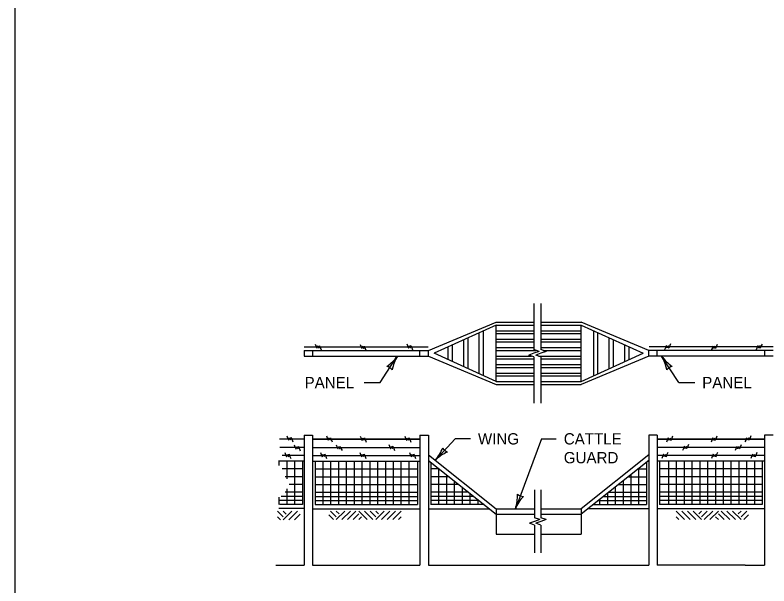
# Model space of a CAD drawing. Extents: x 49991.4 to 50021, y 49987.6 to 50011.4.
# Drawn here: x 49999.384 to 50003.386, y 49992.938 to 49995.969 of the extents above; entities that cross this region are included whole.
import ezdxf

# ---------------------------------------------------------------- set-up
doc = ezdxf.new("R2010")
doc.units = 0
for name, color, linetype in [('Level 1', 7, 'Continuous'), ('Level 2', 7, 'Continuous'), ('Level 3', 7, 'Continuous'), ('Level 4', 7, 'Continuous'), ('Level 6', 7, 'Continuous')]:
    doc.layers.add(name, color=color, linetype=linetype)

msp = doc.modelspace()

# ---------------------------------------------------------------- linework, layer by layer
at = {"layer": 'Level 1'}
for p, q in [((50001.5785, 49994.1885), (50001.9385, 49994.3385)), ((50001.9385, 49994.3235), (50001.6085, 49994.1735)), ((50001.9385, 49994.3385), (50002.1384, 49994.3385)), ((50001.9385, 49994.0235), (50001.9385, 49994.3235)), ((50001.9385, 49994.3235), (50002.1384, 49994.3235)), ((50002.1756, 49994.3385), (50002.3885, 49994.3385)), ((50002.1756, 49994.3235), (50002.3885, 49994.3235)), ((50002.7485, 49994.1885), (50002.3885, 49994.3385)), ((50002.3885, 49994.3235), (50002.7185, 49994.1735)), ((50002.3885, 49994.0235), (50002.3885, 49994.3235)), ((50001.8485, 49994.064), (50001.8485, 49994.2821)), ((50001.871, 49994.0537), (50001.871, 49994.2923)), ((50001.9385, 49994.2935), (50002.1384, 49994.2935)), ((50001.9385, 49994.2785), (50002.1384, 49994.2785)), ((50002.1756, 49994.2935), (50002.3885, 49994.2935)), ((50002.1756, 49994.2785), (50002.3885, 49994.2785)), ((50002.456, 49994.0537), (50002.456, 49994.2923)), ((50002.4785, 49994.064), (50002.4785, 49994.2821)), ((50001.766, 49994.1015), (50001.766, 49994.2443)), ((50001.7885, 49994.0913), (50001.7885, 49994.2554)), ((50001.9385, 49994.2485), (50002.1384, 49994.2485)), ((50001.9385, 49994.2335), (50002.1384, 49994.2335)), ((50002.1756, 49994.2485), (50002.3885, 49994.2485)), ((50002.1756, 49994.2335), (50002.3885, 49994.2335)), ((50002.5385, 49994.0913), (50002.5385, 49994.2554)), ((50002.561, 49994.1015), (50002.561, 49994.2443)), ((50000.9185, 49994.208), (50001.5771, 49994.208)), ((50000.9185, 49994.1885), (50000.9185, 49994.1585)), ((50000.9185, 49994.1885), (50001.5785, 49994.1885)), ((50000.9635, 49994.1885), (50000.9635, 49994.1585)), ((50001.5335, 49994.1585), (50001.5335, 49994.1885)), ((50001.5785, 49994.1585), (50001.5785, 49994.1885)), ((50001.6835, 49994.1389), (50001.6835, 49994.2074)), ((50001.706, 49994.1287), (50001.706, 49994.2176)), ((50001.706, 49994.1287), (50001.706, 49994.2176)), ((50001.9385, 49994.2035), (50002.1384, 49994.2035)), ((50001.9385, 49994.1885), (50002.1508, 49994.1885)), ((50002.1756, 49994.2035), (50002.3885, 49994.2035)), ((50002.188, 49994.1885), (50002.3885, 49994.1885)), ((50002.621, 49994.1287), (50002.621, 49994.2176)), ((50002.621, 49994.1287), (50002.621, 49994.2176)), ((50002.621, 49994.1287), (50002.621, 49994.2176)), ((50002.6435, 49994.1389), (50002.6435, 49994.2074)), ((50002.7485, 49994.1585), (50002.7485, 49994.1885)), ((50003.4085, 49994.1885), (50002.7485, 49994.1885)), ((50003.4085, 49994.208), (50002.7499, 49994.208)), ((50002.7935, 49994.1585), (50002.7935, 49994.1885)), ((50003.3635, 49994.1885), (50003.3635, 49994.1585)), ((50000.9185, 49994.1585), (50001.5785, 49994.1585)), ((50001.5785, 49994.1585), (50001.9385, 49994.0085)), ((50001.9385, 49994.0235), (50001.6085, 49994.1735)), ((50001.9385, 49994.1585), (50002.126, 49994.1585)), ((50002.1632, 49994.1585), (50002.3885, 49994.1585)), ((50002.3885, 49994.0235), (50002.7185, 49994.1735)), ((50002.7485, 49994.1585), (50002.3885, 49994.0085)), ((50003.4085, 49994.1585), (50002.7485, 49994.1585)), ((50001.9385, 49994.1435), (50002.1384, 49994.1435)), ((50001.9385, 49994.1135), (50002.1384, 49994.1135)), ((50002.1756, 49994.1435), (50002.3885, 49994.1435)), ((50002.1756, 49994.1135), (50002.3885, 49994.1135)), ((50001.9385, 49994.0985), (50002.1384, 49994.0985)), ((50001.9385, 49994.0685), (50002.1384, 49994.0685)), ((50002.1756, 49994.0985), (50002.3885, 49994.0985)), ((50002.1756, 49994.0685), (50002.3885, 49994.0685)), ((50001.9385, 49994.0535), (50002.1384, 49994.0535)), ((50002.1756, 49994.0535), (50002.3885, 49994.0535)), ((50001.9385, 49994.0235), (50002.1384, 49994.0235)), ((50001.9385, 49994.0085), (50002.1384, 49994.0085)), ((50002.1756, 49994.0235), (50002.3885, 49994.0235)), ((50002.1756, 49994.0085), (50002.3885, 49994.0085)), ((50000.9185, 49993.7184), (50000.7881, 49993.7184)), ((50000.918, 49993.7169), (50000.918, 49993.7169)), ((50000.9185, 49993.7385), (50000.9635, 49993.7385)), ((50000.9185, 49993.7385), (50000.9185, 49993.3485)), ((50000.9185, 49993.7235), (50000.9185, 49993.7235)), ((50001.5306, 49993.7177), (50000.963, 49993.7177)), ((50000.9635, 49993.7385), (50000.9635, 49993.3485)), ((50000.9635, 49993.7169), (50001.5335, 49993.7169)), ((50001.5335, 49993.7385), (50001.5335, 49993.3485)), ((50001.5335, 49993.7385), (50001.5785, 49993.7385)), ((50001.5785, 49993.7385), (50001.5785, 49993.3485)), ((50002.7935, 49993.7385), (50002.7485, 49993.7385)), ((50002.7485, 49993.7385), (50002.7485, 49993.3485)), ((50002.7935, 49993.7385), (50002.7935, 49993.3485)), ((50003.3635, 49993.7169), (50002.7935, 49993.7169)), ((50002.7964, 49993.7177), (50003.364, 49993.7177)), ((50003.3635, 49993.7385), (50003.3635, 49993.3485)), ((50003.4085, 49993.7385), (50003.3635, 49993.7385)), ((50000.918, 49993.6736), (50000.7889, 49993.6736)), ((50000.918, 49993.6736), (50000.9185, 49993.6736)), ((50000.9635, 49993.6736), (50001.5345, 49993.6736)), ((50003.3635, 49993.6736), (50002.7925, 49993.6736)), ((50000.918, 49993.6302), (50000.8021, 49993.6302)), ((50000.918, 49993.6302), (50000.9185, 49993.6302)), ((50000.9635, 49993.6302), (50001.5335, 49993.6302)), ((50001.5785, 49993.6335), (50001.9385, 49993.3485)), ((50002.7485, 49993.6335), (50002.3885, 49993.3485)), ((50003.3635, 49993.6302), (50002.7935, 49993.6302)), ((50000.918, 49993.6014), (50000.7821, 49993.6014)), ((50000.7848, 49993.6014), (50000.7848, 49993.5778)), ((50000.8263, 49993.6014), (50000.8263, 49993.5071)), ((50000.8678, 49993.6014), (50000.8678, 49993.3704)), ((50000.9093, 49993.6014), (50000.9093, 49993.3704)), ((50000.9635, 49993.6014), (50001.5207, 49993.6014)), ((50000.9761, 49993.6014), (50000.9761, 49993.3704)), ((50001.0176, 49993.6014), (50001.0176, 49993.3704)), ((50001.0591, 49993.6014), (50001.0591, 49993.3704)), ((50001.1006, 49993.6014), (50001.1006, 49993.3704)), ((50001.1421, 49993.6014), (50001.1421, 49993.3704)), ((50001.1836, 49993.6014), (50001.1836, 49993.3704)), ((50001.2251, 49993.6014), (50001.2251, 49993.3704)), ((50001.2666, 49993.6014), (50001.2666, 49993.3704)), ((50001.3081, 49993.6014), (50001.3081, 49993.3704)), ((50001.3496, 49993.6014), (50001.3496, 49993.3704)), ((50001.3911, 49993.6014), (50001.3911, 49993.3704)), ((50001.4326, 49993.6014), (50001.4326, 49993.3704)), ((50001.4741, 49993.6014), (50001.4741, 49993.3704)), ((50001.521, 49993.6014), (50001.521, 49993.5749)), ((50001.521, 49993.6014), (50001.5335, 49993.6014)), ((50001.5812, 49993.6014), (50001.5782, 49993.6014)), ((50001.5785, 49993.6035), (50001.9385, 49993.3185)), ((50001.5785, 49993.6014), (50001.5785, 49993.3605)), ((50001.5909, 49993.5924), (50001.5909, 49993.3704)), ((50002.7485, 49993.6035), (50002.3885, 49993.3185)), ((50002.7361, 49993.5924), (50002.7361, 49993.3704)), ((50002.7458, 49993.6014), (50002.7488, 49993.6014)), ((50002.7458, 49993.6014), (50002.7488, 49993.6014)), ((50002.7485, 49993.6014), (50002.7485, 49993.3605)), ((50002.7485, 49993.6014), (50002.7485, 49993.3605)), ((50002.806, 49993.6014), (50002.7935, 49993.6014)), ((50002.806, 49993.6014), (50002.806, 49993.5749)), ((50003.3635, 49993.6014), (50002.8063, 49993.6014)), ((50002.8529, 49993.6014), (50002.8529, 49993.3704)), ((50002.8944, 49993.6014), (50002.8944, 49993.3704)), ((50002.9359, 49993.6014), (50002.9359, 49993.3704)), ((50002.9774, 49993.6014), (50002.9774, 49993.3704)), ((50003.0189, 49993.6014), (50003.0189, 49993.3704)), ((50003.0604, 49993.6014), (50003.0604, 49993.3704)), ((50003.1019, 49993.6014), (50003.1019, 49993.3704)), ((50003.1434, 49993.6014), (50003.1434, 49993.3704)), ((50003.1849, 49993.6014), (50003.1849, 49993.3704)), ((50003.2264, 49993.6014), (50003.2264, 49993.3704)), ((50003.2679, 49993.6014), (50003.2679, 49993.3704)), ((50003.3094, 49993.6014), (50003.3094, 49993.3704)), ((50003.3509, 49993.6014), (50003.3509, 49993.3704)), ((50000.9093, 49993.5599), (50000.8016, 49993.5599)), ((50000.9761, 49993.5599), (50001.5207, 49993.5599)), ((50001.521, 49993.5749), (50001.521, 49993.3704)), ((50001.6339, 49993.5599), (50001.5914, 49993.5599)), ((50001.6324, 49993.5598), (50001.6324, 49993.3704)), ((50002.6931, 49993.5599), (50002.7356, 49993.5599)), ((50002.6946, 49993.5598), (50002.6946, 49993.3704)), ((50002.806, 49993.5749), (50002.806, 49993.3704)), ((50003.3509, 49993.5599), (50002.8063, 49993.5599)), ((50000.9093, 49993.5184), (50000.8182, 49993.5184)), ((50000.9761, 49993.5184), (50001.5207, 49993.5184)), ((50001.6847, 49993.5184), (50001.5906, 49993.5184)), ((50001.6739, 49993.5262), (50001.6739, 49993.3704)), ((50002.6423, 49993.5184), (50002.7364, 49993.5184)), ((50002.6531, 49993.5262), (50002.6531, 49993.3704)), ((50003.3509, 49993.5184), (50002.8063, 49993.5184)), ((50000.9093, 49993.4769), (50000.8394, 49993.4769)), ((50000.9761, 49993.4769), (50001.5207, 49993.4769)), ((50001.7376, 49993.4769), (50001.5906, 49993.4769)), ((50001.7154, 49993.4947), (50001.7154, 49993.3704)), ((50002.5894, 49993.4769), (50002.7364, 49993.4769)), ((50002.6116, 49993.4947), (50002.6116, 49993.3704)), ((50003.3509, 49993.4769), (50002.8063, 49993.4769)), ((50000.9093, 49993.4354), (50000.8171, 49993.4354)), ((50000.8263, 49993.4542), (50000.8263, 49993.3704)), ((50000.9761, 49993.4354), (50001.5207, 49993.4354)), ((50001.7884, 49993.4354), (50001.5906, 49993.4354)), ((50001.7569, 49993.461), (50001.7569, 49993.3704)), ((50001.7985, 49993.429), (50001.7985, 49993.3704)), ((50002.5285, 49993.429), (50002.5285, 49993.3704)), ((50002.5386, 49993.4354), (50002.7364, 49993.4354)), ((50002.5701, 49993.461), (50002.5701, 49993.3704)), ((50003.3509, 49993.4354), (50002.8063, 49993.4354)), ((50000.9093, 49993.392), (50000.7818, 49993.392)), ((50000.7848, 49993.4089), (50000.7848, 49993.3704)), ((50000.9093, 49993.4137), (50000.7972, 49993.4137)), ((50000.9761, 49993.4137), (50001.5206, 49993.4137)), ((50000.9761, 49993.392), (50001.5212, 49993.392)), ((50001.8453, 49993.392), (50001.5908, 49993.392)), ((50001.8183, 49993.4137), (50001.5914, 49993.4137)), ((50001.8399, 49993.3965), (50001.8399, 49993.3704)), ((50002.4817, 49993.392), (50002.7362, 49993.392)), ((50002.4871, 49993.3965), (50002.4871, 49993.3704)), ((50002.5087, 49993.4137), (50002.7356, 49993.4137)), ((50003.3509, 49993.392), (50002.8058, 49993.392)), ((50003.3509, 49993.4137), (50002.8064, 49993.4137)), ((50000.918, 49993.3486), (50000.7844, 49993.3486)), ((50000.9093, 49993.3704), (50000.7889, 49993.3704)), ((50000.9635, 49993.3485), (50001.5335, 49993.3485)), ((50000.9761, 49993.3704), (50001.5209, 49993.3704)), ((50001.5785, 49993.3485), (50001.8992, 49993.3485)), ((50001.8735, 49993.3704), (50001.5912, 49993.3704)), ((50001.9385, 49993.3485), (50001.9385, 49993.3185)), ((50001.9385, 49993.3485), (50002.1416, 49993.3485)), ((50002.176, 49993.3485), (50002.3885, 49993.3485)), ((50002.3885, 49993.3485), (50002.3885, 49993.3185)), ((50002.7485, 49993.3485), (50002.4278, 49993.3485)), ((50002.4535, 49993.3704), (50002.7358, 49993.3704)), ((50003.3635, 49993.3485), (50002.7935, 49993.3485)), ((50003.3509, 49993.3704), (50002.8061, 49993.3704)), ((50000.8075, 49993.3048), (50000.7775, 49993.3348)), ((50000.8075, 49993.2898), (50000.8525, 49993.3348)), ((50000.8075, 49993.2898), (50000.8525, 49993.3348)), ((50000.8225, 49993.3198), (50000.8075, 49993.3348)), ((50000.8375, 49993.2898), (50000.8825, 49993.3348)), ((50000.8375, 49993.2898), (50000.8825, 49993.3348)), ((50000.8675, 49993.2898), (50000.8966, 49993.3189)), ((50001.0737, 49993.2909), (50001.0496, 49993.315)), ((50001.0887, 49993.3059), (50001.0587, 49993.3359)), ((50001.0887, 49993.2909), (50001.1337, 49993.3359)), ((50001.0887, 49993.2909), (50001.1337, 49993.3359)), ((50001.1037, 49993.3209), (50001.0887, 49993.3359)), ((50001.1187, 49993.2909), (50001.1637, 49993.3359)), ((50001.1187, 49993.2909), (50001.1637, 49993.3359)), ((50001.1487, 49993.2909), (50001.1937, 49993.3359)), ((50001.1487, 49993.2909), (50001.1937, 49993.3359)), ((50001.1787, 49993.2909), (50001.2087, 49993.3209)), ((50001.2537, 49993.2909), (50001.2087, 49993.3359)), ((50001.2837, 49993.2909), (50001.2387, 49993.3359)), ((50001.2987, 49993.3059), (50001.2687, 49993.3359)), ((50001.2987, 49993.2909), (50001.3437, 49993.3359)), ((50001.2987, 49993.2909), (50001.3437, 49993.3359)), ((50001.3137, 49993.3209), (50001.2987, 49993.3359)), ((50001.3287, 49993.2909), (50001.3737, 49993.3359)), ((50001.3287, 49993.2909), (50001.3737, 49993.3359)), ((50001.3587, 49993.2909), (50001.4037, 49993.3359)), ((50001.3587, 49993.2909), (50001.4037, 49993.3359)), ((50001.3887, 49993.2909), (50001.4337, 49993.3359)), ((50001.3887, 49993.2909), (50001.4337, 49993.3359)), ((50001.9385, 49993.3185), (50002.1416, 49993.3185)), ((50002.176, 49993.3185), (50002.3885, 49993.3185)), ((50002.9383, 49993.2909), (50002.8933, 49993.3359)), ((50002.9383, 49993.2909), (50002.8933, 49993.3359)), ((50002.9683, 49993.2909), (50002.9233, 49993.3359)), ((50002.9683, 49993.2909), (50002.9233, 49993.3359)), ((50002.9983, 49993.2909), (50002.9533, 49993.3359)), ((50002.9983, 49993.2909), (50002.9533, 49993.3359)), ((50003.0283, 49993.2909), (50002.9833, 49993.3359)), ((50003.0283, 49993.2909), (50002.9833, 49993.3359)), ((50003.0133, 49993.3209), (50003.0283, 49993.3359)), ((50003.0283, 49993.3059), (50003.0583, 49993.3359)), ((50003.0433, 49993.2909), (50003.0883, 49993.3359)), ((50003.0733, 49993.2909), (50003.1183, 49993.3359)), ((50003.1483, 49993.2909), (50003.1183, 49993.3209)), ((50003.1783, 49993.2909), (50003.1333, 49993.3359)), ((50003.1783, 49993.2909), (50003.1333, 49993.3359)), ((50003.2083, 49993.2909), (50003.1633, 49993.3359)), ((50003.2083, 49993.2909), (50003.1633, 49993.3359)), ((50003.2383, 49993.2909), (50003.1933, 49993.3359)), ((50003.2383, 49993.2909), (50003.1933, 49993.3359)), ((50003.2233, 49993.3209), (50003.2383, 49993.3359)), ((50003.2383, 49993.3059), (50003.2683, 49993.3359)), ((50003.2533, 49993.2909), (50003.2774, 49993.315)), ((50000.7925, 49993.2898), (50000.7767, 49993.3056)), ((50000.8675, 49993.2898), (50000.8795, 49993.3018)), ((50001.2087, 49993.2909), (50001.2237, 49993.3059)), ((50001.4187, 49993.2909), (50001.4337, 49993.3059)), ((50002.9083, 49993.2909), (50002.8933, 49993.3059)), ((50003.1183, 49993.2909), (50003.1033, 49993.3059))]:
    msp.add_line(p, q, dxfattribs=at)
msp.add_lwpolyline([(49999.3835, 49998.9992), (50016.7501, 49998.9992), (50016.7501, 49987.7988), (49999.3835, 49987.7988)], close=True, dxfattribs=at)
for points in [[(50000.9773, 49994.2227), (50000.9878, 49994.2017), (50000.9878, 49994.2122), (50000.9983, 49994.2017), (50000.9983, 49994.2122), (50001.0088, 49994.1912)], [(50001.2153, 49994.2209), (50001.2258, 49994.1999), (50001.2258, 49994.2104), (50001.2363, 49994.1999), (50001.2363, 49994.2104), (50001.2468, 49994.1894)], [(50001.463, 49994.2239), (50001.4735, 49994.2029), (50001.4735, 49994.2134), (50001.484, 49994.2029), (50001.484, 49994.2134), (50001.4945, 49994.1924)], [(50002.864, 49994.2239), (50002.8535, 49994.2029), (50002.8535, 49994.2134), (50002.843, 49994.2029), (50002.843, 49994.2134), (50002.8325, 49994.1924)], [(50003.1117, 49994.2209), (50003.1012, 49994.1999), (50003.1012, 49994.2104), (50003.0907, 49994.1999), (50003.0907, 49994.2104), (50003.0802, 49994.1894)], [(50003.3497, 49994.2227), (50003.3392, 49994.2017), (50003.3392, 49994.2122), (50003.3287, 49994.2017), (50003.3287, 49994.2122), (50003.3182, 49994.1912)], [(50000.8267, 49993.7352), (50000.8372, 49993.7142), (50000.8372, 49993.7247), (50000.8477, 49993.7142), (50000.8477, 49993.7247), (50000.8582, 49993.7037)], [(50001.0365, 49993.7345), (50001.047, 49993.7135), (50001.047, 49993.724), (50001.0575, 49993.7135), (50001.0575, 49993.724), (50001.068, 49993.703)], [(50001.2167, 49993.7334), (50001.2272, 49993.7124), (50001.2272, 49993.7229), (50001.2377, 49993.7124), (50001.2377, 49993.7229), (50001.2482, 49993.7019)], [(50001.4531, 49993.7337), (50001.4636, 49993.7126), (50001.4636, 49993.7232), (50001.4741, 49993.7126), (50001.4741, 49993.7232), (50001.4846, 49993.7021)], [(50002.8739, 49993.7337), (50002.8634, 49993.7126), (50002.8634, 49993.7232), (50002.8529, 49993.7126), (50002.8529, 49993.7232), (50002.8424, 49993.7021)], [(50003.1103, 49993.7334), (50003.0998, 49993.7124), (50003.0998, 49993.7229), (50003.0893, 49993.7124), (50003.0893, 49993.7229), (50003.0788, 49993.7019)], [(50003.2905, 49993.7345), (50003.28, 49993.7135), (50003.28, 49993.724), (50003.2695, 49993.7135), (50003.2695, 49993.724), (50003.259, 49993.703)], [(50000.8655, 49993.6874), (50000.876, 49993.6664), (50000.876, 49993.6769), (50000.8865, 49993.6664), (50000.8865, 49993.6769), (50000.897, 49993.6559)], [(50001.0881, 49993.6881), (50001.0986, 49993.6671), (50001.0986, 49993.6776), (50001.1091, 49993.6671), (50001.1091, 49993.6776), (50001.1196, 49993.6566)], [(50001.3674, 49993.6896), (50001.3779, 49993.6686), (50001.3779, 49993.6791), (50001.3884, 49993.6686), (50001.3884, 49993.6791), (50001.3989, 49993.6581)], [(50002.9596, 49993.6896), (50002.9491, 49993.6686), (50002.9491, 49993.6791), (50002.9386, 49993.6686), (50002.9386, 49993.6791), (50002.9281, 49993.6581)], [(50003.2389, 49993.6881), (50003.2284, 49993.6671), (50003.2284, 49993.6776), (50003.2179, 49993.6671), (50003.2179, 49993.6776), (50003.2074, 49993.6566)], [(50000.8156, 49993.6464), (50000.8261, 49993.6254), (50000.8261, 49993.6359), (50000.8366, 49993.6254), (50000.8366, 49993.6359), (50000.8471, 49993.6149)], [(50001.0052, 49993.6464), (50001.0157, 49993.6254), (50001.0157, 49993.6359), (50001.0262, 49993.6254), (50001.0262, 49993.6359), (50001.0367, 49993.6149)], [(50001.2143, 49993.6464), (50001.2248, 49993.6254), (50001.2248, 49993.6359), (50001.2353, 49993.6254), (50001.2353, 49993.6359), (50001.2458, 49993.6149)], [(50001.478, 49993.6464), (50001.4885, 49993.6254), (50001.4885, 49993.6359), (50001.499, 49993.6254), (50001.499, 49993.6359), (50001.5095, 49993.6149)], [(50002.849, 49993.6464), (50002.8385, 49993.6254), (50002.8385, 49993.6359), (50002.828, 49993.6254), (50002.828, 49993.6359), (50002.8175, 49993.6149)], [(50003.1127, 49993.6464), (50003.1022, 49993.6254), (50003.1022, 49993.6359), (50003.0917, 49993.6254), (50003.0917, 49993.6359), (50003.0812, 49993.6149)], [(50003.3218, 49993.6464), (50003.3113, 49993.6254), (50003.3113, 49993.6359), (50003.3008, 49993.6254), (50003.3008, 49993.6359), (50003.2903, 49993.6149)]]:
    msp.add_spline(points, degree=3, dxfattribs=at)
at = {"layer": 'Level 3'}
for p, q in [((50001.3223, 49994.0179), (50001.4132, 49994.1585)), ((50002.9074, 49994.0179), (50002.8166, 49994.1585)), ((50001.2376, 49994.0179), (50001.3223, 49994.0179)), ((50002.9074, 49994.0179), (50002.9921, 49994.0179)), ((50001.7208, 49993.7193), (50001.6146, 49993.605)), ((50001.8012, 49993.7193), (50001.7208, 49993.7193)), ((50002.1781, 49993.7193), (50002.04, 49993.3485)), ((50002.1781, 49993.7193), (50002.2571, 49993.7193))]:
    msp.add_line(p, q, dxfattribs=at)
for centre, radius, start, end in [((50001.2317, 49994.2868), 0.2223, 304.5727, 324.7562), ((50001.6149, 49994.0418), 0.233, 149.944, 169.1939), ((50002.6251, 49994.0457), 0.2223, 10.3007, 30.4842), ((50003.0059, 49994.2944), 0.233, 215.672, 234.9218), ((50001.3436, 49994.0508), 0.0548, 39.2555, 74.9779), ((50002.8862, 49994.0508), 0.0548, 104.9835, 140.7059), ((50001.4363, 49993.7549), 0.233, 319.941, 339.1908), ((50001.7019, 49993.6989), 0.0548, 209.2525, 244.9748), ((50001.7711, 49993.4471), 0.2223, 114.5697, 134.7532), ((50001.818, 49993.4189), 0.233, 342.4001, 1.6499), ((50002.245, 49993.2624), 0.2223, 137.0288, 157.2123), ((50002.0848, 49993.4686), 0.0548, 231.7116, 267.4339)]:
    msp.add_arc(centre, radius, start, end, dxfattribs=at)
at = {"layer": 'Level 4'}
for p, q in [((50000.9185, 49993.3485), (50000.9185, 49993.0485)), ((50000.9635, 49993.3485), (50000.9635, 49993.0485)), ((50001.5335, 49993.3485), (50001.5335, 49993.0485)), ((50001.5785, 49993.3485), (50001.5785, 49993.0485)), ((50002.7485, 49993.3485), (50002.7485, 49993.0485)), ((50002.7935, 49993.3485), (50002.7935, 49993.0485)), ((50003.3635, 49993.3485), (50003.3635, 49993.0485)), ((50001.9385, 49993.3185), (50001.9385, 49993.2135)), ((50002.3885, 49993.3185), (50002.3885, 49993.2135)), ((50001.9385, 49993.2135), (50002.1416, 49993.2135)), ((50002.176, 49993.2135), (50002.3885, 49993.2135)), ((50000.7685, 49993.0485), (50000.9185, 49993.0485)), ((50000.9635, 49993.0485), (50001.5335, 49993.0485)), ((50001.5785, 49993.0485), (50002.7485, 49993.0485)), ((50003.2596, 49993.0485), (50002.7935, 49993.0485)), ((50003.2596, 49993.0485), (50003.3635, 49993.0485))]:
    msp.add_line(p, q, dxfattribs=at)
at = {"layer": 'Level 6'}
for p, q in [((50002.1384, 49994.4385), (50002.1384, 49994.1929)), ((50002.1756, 49994.4385), (50002.1756, 49994.1929)), ((50002.1658, 49994.1832), (50002.1384, 49994.1929)), ((50002.203, 49994.1832), (50002.1756, 49994.1929)), ((50002.1384, 49994.1735), (50002.111, 49994.1638)), ((50002.1384, 49994.1541), (50002.111, 49994.1638)), ((50002.1658, 49994.1832), (50002.1384, 49994.1735)), ((50002.1384, 49994.1541), (50002.1384, 49993.9085)), ((50002.1756, 49994.1735), (50002.1482, 49994.1638)), ((50002.1756, 49994.1541), (50002.1482, 49994.1638)), ((50002.203, 49994.1832), (50002.1756, 49994.1735)), ((50002.1756, 49994.1541), (50002.1756, 49993.9085)), ((50002.1416, 49993.4485), (50002.1416, 49993.3004)), ((50002.176, 49993.4485), (50002.176, 49993.3004)), ((50002.1416, 49993.281), (50002.1142, 49993.2713)), ((50002.1416, 49993.2616), (50002.1142, 49993.2713)), ((50002.169, 49993.2907), (50002.1416, 49993.3004)), ((50002.169, 49993.2907), (50002.1416, 49993.281)), ((50002.176, 49993.281), (50002.1486, 49993.2713)), ((50002.176, 49993.2616), (50002.1486, 49993.2713)), ((50002.2034, 49993.2907), (50002.176, 49993.3004)), ((50002.2034, 49993.2907), (50002.176, 49993.281)), ((50002.1416, 49993.2616), (50002.1416, 49993.1135)), ((50002.176, 49993.2616), (50002.176, 49993.1135))]:
    msp.add_line(p, q, dxfattribs=at)

# ---------------------------------------------------------------- texts
at = {"layer": 'Level 2'}
for s, p in [('PANEL', (50000.9208, 49993.9879)), ('PANEL', (50003.0321, 49993.9879)), ('WING', (50001.8412, 49993.6893)), ('CATTLE', (50002.2971, 49993.6893)), ('GUARD', (50002.2971, 49993.5893))]:
    msp.add_text(s, height=0.06, dxfattribs=at).set_placement(p)

doc.saveas('drawing.dxf')
